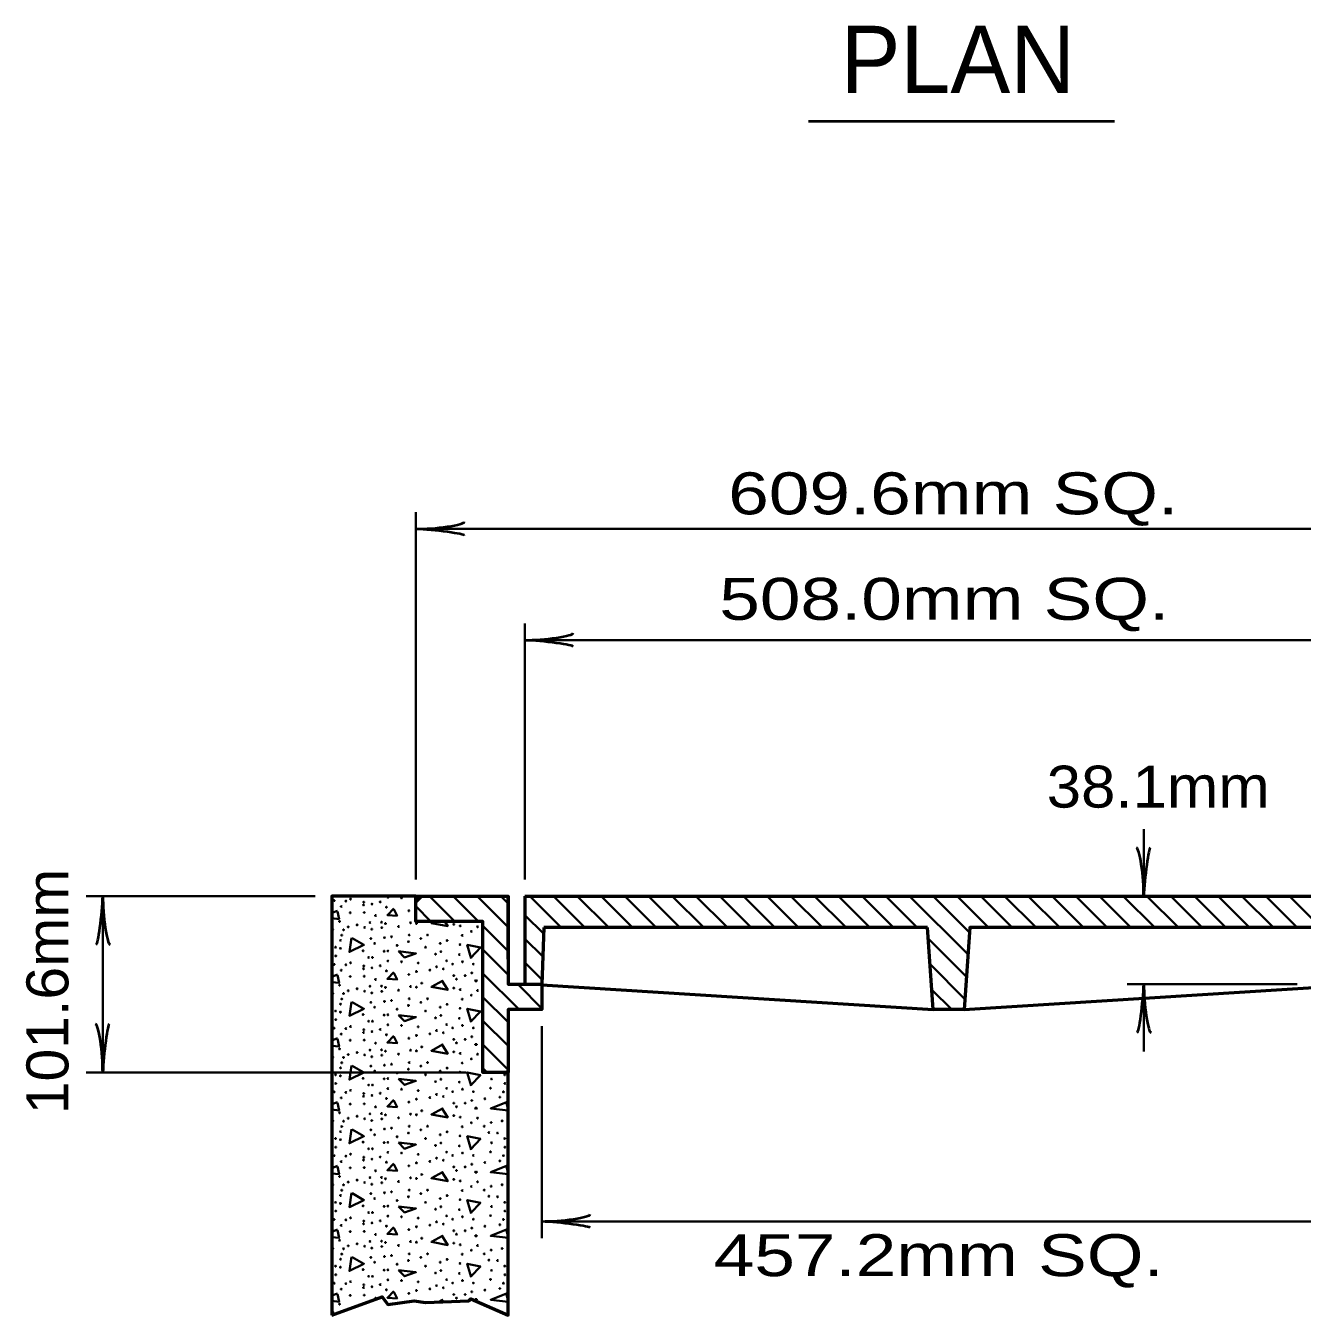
# Model space of a CAD drawing. Extents: x 918 to 1774, y -8 to 536.
# Drawn here: x 1316.9 to 1408.1, y 260.9 to 353.1 of the extents above; entities that cross this region are included whole.
import ezdxf

# ---------------------------------------------------------------- set-up
doc = ezdxf.new("R2010")
doc.units = 0
doc.header["$LTSCALE"] = 1.2
doc.layers.add('1', color=7, linetype='Continuous', lineweight=35)

msp = doc.modelspace()

# ---------------------------------------------------------------- linework, layer by layer
at = {"layer": '1', "lineweight": 40}
msp.add_line((1372.846, 346.241), (1394.731, 346.241), dxfattribs=at)
at = {"layer": '1'}
for p, q in [((1344.782, 292.018), (1344.782, 318.275)), ((1344.782, 317.075), (1420.982, 317.075)), ((1352.582, 292.018), (1352.582, 310.322)), ((1352.582, 309.122), (1413.182, 309.122)), ((1396.822, 290.818), (1396.822, 295.618)), ((1337.582, 290.818), (1321.204, 290.818)), ((1322.404, 290.818), (1322.404, 278.218)), ((1347.562, 289.018), (1345.762, 290.818)), ((1349.259, 289.018), (1347.459, 290.818)), ((1351.382, 288.591), (1349.156, 290.818)), ((1351.382, 290.288), (1350.853, 290.818)), ((1352.927, 290.818), (1355.177, 288.568)), ((1354.624, 290.818), (1356.874, 288.568)), ((1356.322, 290.818), (1358.572, 288.568)), ((1358.019, 290.818), (1360.269, 288.568)), ((1359.716, 290.818), (1361.966, 288.568)), ((1361.413, 290.818), (1363.663, 288.568)), ((1363.11, 290.818), (1365.36, 288.568)), ((1364.807, 290.818), (1367.057, 288.568)), ((1366.504, 290.818), (1368.754, 288.568)), ((1368.201, 290.818), (1370.451, 288.568)), ((1369.898, 290.818), (1372.148, 288.568)), ((1371.595, 290.818), (1373.845, 288.568)), ((1373.292, 290.818), (1375.542, 288.568)), ((1374.989, 290.818), (1377.239, 288.568)), ((1376.686, 290.818), (1378.936, 288.568)), ((1378.383, 290.818), (1380.633, 288.568)), ((1380.08, 290.818), (1384.26, 286.638)), ((1381.777, 290.818), (1384.369, 288.226)), ((1383.474, 290.818), (1385.724, 288.568)), ((1385.171, 290.818), (1387.421, 288.568)), ((1386.869, 290.818), (1389.119, 288.568)), ((1388.566, 290.818), (1390.816, 288.568)), ((1390.263, 290.818), (1392.513, 288.568)), ((1391.96, 290.818), (1394.21, 288.568)), ((1393.657, 290.818), (1395.907, 288.568)), ((1395.354, 290.818), (1397.604, 288.568)), ((1397.051, 290.818), (1399.301, 288.568)), ((1398.748, 290.818), (1400.998, 288.568)), ((1400.445, 290.818), (1402.695, 288.568)), ((1402.142, 290.818), (1404.392, 288.568)), ((1403.839, 290.818), (1406.089, 288.568)), ((1405.536, 290.818), (1407.786, 288.568)), ((1407.233, 290.818), (1409.483, 288.568)), ((1339.172, 289.778), (1338.782, 289.621)), ((1345.865, 289.018), (1344.782, 290.1)), ((1351.382, 286.894), (1349.582, 288.694)), ((1352.582, 289.466), (1353.921, 288.127)), ((1352.582, 287.769), (1353.858, 286.493)), ((1381.427, 287.774), (1384.15, 285.051)), ((1351.382, 285.197), (1349.582, 286.997)), ((1352.582, 286.072), (1353.796, 284.858)), ((1381.552, 285.952), (1384.041, 283.463)), ((1339.172, 285.218), (1338.782, 285.061)), ((1352.165, 282.718), (1349.582, 285.3)), ((1353.862, 282.718), (1352.062, 284.518)), ((1381.678, 284.128), (1383.089, 282.718)), ((1407.782, 284.518), (1395.623, 284.518)), ((1396.822, 279.718), (1396.822, 284.518)), ((1351.382, 281.803), (1349.582, 283.603)), ((1351.382, 280.106), (1349.582, 281.906)), ((1353.782, 281.518), (1353.782, 266.367)), ((1339.172, 280.658), (1338.782, 280.501)), ((1351.382, 278.409), (1349.582, 280.209)), ((1349.877, 278.218), (1349.582, 278.512)), ((1348.382, 278.218), (1321.204, 278.218)), ((1339.172, 276.098), (1338.782, 275.941)), ((1351.382, 275.526), (1351.268, 276.05)), ((1339.172, 271.538), (1338.782, 271.381)), ((1351.382, 270.966), (1351.268, 271.49)), ((1353.782, 267.567), (1411.982, 267.567)), ((1339.172, 266.978), (1338.782, 266.821)), ((1351.382, 266.406), (1351.268, 266.93)), ((1339.172, 262.418), (1338.782, 262.261)), ((1346.684, 261.962), (1346.38, 261.796)), ((1346.748, 261.812), (1346.636, 261.986)), ((1351.382, 261.846), (1351.268, 262.37))]:
    msp.add_line(p, q, dxfattribs=at)
at = {"layer": '1', "lineweight": 53}
for p, q in [((1345.187, 290.818), (1344.782, 290.413)), ((1351.382, 286.318), (1351.382, 290.818)), ((1352.582, 290.818), (1413.182, 290.818)), ((1352.582, 290.818), (1352.582, 284.518)), ((1353.938, 288.568), (1353.782, 284.495)), ((1381.372, 288.568), (1353.938, 288.568)), ((1353.783, 284.48), (1381.775, 282.718)), ((1383.989, 282.718), (1411.982, 284.48)), ((1351.382, 278.345), (1351.255, 278.218))]:
    msp.add_line(p, q, dxfattribs=at)
for points in [[(1344.782, 290.818), (1338.782, 290.818), (1338.782, 260.855)], [(1338.782, 260.855), (1342.37, 262.162), (1342.775, 261.622), (1344.663, 261.892), (1344.663, 261.892), (1345.473, 261.757), (1348.575, 261.892), (1348.71, 262.027), (1351.382, 260.855), (1351.382, 278.218), (1349.582, 278.218), (1349.582, 289.018), (1344.782, 289.018), (1344.782, 290.818)], [(1411.827, 288.568), (1384.393, 288.568), (1383.989, 282.718), (1381.775, 282.718), (1381.372, 288.568)]]:
    msp.add_lwpolyline(points, dxfattribs=at)
msp.add_lwpolyline([(1344.782, 290.818), (1351.382, 290.818), (1351.382, 284.518), (1353.783, 284.518), (1353.783, 282.718), (1351.382, 282.718), (1351.382, 278.218), (1349.582, 278.218), (1349.582, 289.018), (1344.782, 289.018)], close=True, dxfattribs=at)
at = {"layer": '1'}
for points in [[(1338.782, 289.237), (1339.292, 289.178), (1339.172, 289.73)], [(1343.204, 289.946), (1342.748, 289.466), (1343.444, 289.418), (1343.204, 289.898)], [(1346.126, 289.018), (1345.892, 288.89), (1347.068, 288.674), (1346.848, 289.018)], [(1340.228, 287.81), (1341.068, 287.33), (1340.036, 286.826), (1340.18, 287.834)], [(1348.748, 286.37), (1348.46, 287.33), (1349.396, 287.138), (1348.724, 286.418)], [(1338.782, 284.677), (1339.292, 284.618), (1339.172, 285.17)], [(1343.204, 285.386), (1342.748, 284.906), (1343.444, 284.858), (1343.204, 285.338)], [(1346.684, 284.762), (1345.892, 284.33), (1347.068, 284.114), (1346.636, 284.786)], [(1340.228, 283.25), (1341.068, 282.77), (1340.036, 282.266), (1340.18, 283.274)], [(1348.748, 281.81), (1348.46, 282.77), (1349.396, 282.578), (1348.724, 281.858)], [(1338.782, 280.117), (1339.292, 280.058), (1339.172, 280.61)], [(1343.204, 280.826), (1342.748, 280.346), (1343.444, 280.298), (1343.204, 280.778)], [(1346.684, 280.202), (1345.892, 279.77), (1347.068, 279.554), (1346.636, 280.226)], [(1340.228, 278.69), (1341.068, 278.21), (1340.036, 277.706), (1340.18, 278.714)], [(1348.748, 277.25), (1348.46, 278.21), (1349.396, 278.018), (1348.724, 277.298)], [(1338.782, 275.557), (1339.292, 275.498), (1339.172, 276.05)], [(1343.204, 276.266), (1342.748, 275.786), (1343.444, 275.738), (1343.204, 276.218)], [(1351.268, 276.098), (1350.14, 275.642), (1351.382, 275.499)], [(1346.684, 275.642), (1345.892, 275.21), (1347.068, 274.994), (1346.636, 275.666)], [(1340.228, 274.13), (1341.068, 273.65), (1340.036, 273.146), (1340.18, 274.154)], [(1348.748, 272.69), (1348.46, 273.65), (1349.396, 273.458), (1348.724, 272.738)], [(1338.782, 270.997), (1339.292, 270.938), (1339.172, 271.49)], [(1343.204, 271.706), (1342.748, 271.226), (1343.444, 271.178), (1343.204, 271.658)], [(1346.684, 271.082), (1345.892, 270.65), (1347.068, 270.434), (1346.636, 271.106)], [(1351.268, 271.538), (1350.14, 271.082), (1351.382, 270.939)], [(1340.228, 269.57), (1341.068, 269.09), (1340.036, 268.586), (1340.18, 269.594)], [(1348.748, 268.13), (1348.46, 269.09), (1349.396, 268.898), (1348.724, 268.178)], [(1338.782, 266.437), (1339.292, 266.378), (1339.172, 266.93)], [(1343.204, 267.146), (1342.748, 266.666), (1343.444, 266.618), (1343.204, 267.098)], [(1346.684, 266.522), (1345.892, 266.09), (1347.068, 265.874), (1346.636, 266.546)], [(1351.268, 266.978), (1350.14, 266.522), (1351.382, 266.379)], [(1340.228, 265.01), (1341.068, 264.53), (1340.036, 264.026), (1340.18, 265.034)], [(1348.748, 263.57), (1348.46, 264.53), (1349.396, 264.338), (1348.724, 263.618)], [(1338.782, 261.877), (1339.292, 261.818), (1339.172, 262.37)], [(1343.204, 262.586), (1342.748, 262.106), (1343.444, 262.058), (1343.204, 262.538)], [(1351.268, 262.418), (1350.14, 261.962), (1351.382, 261.819)]]:
    msp.add_lwpolyline(points, dxfattribs=at)
for points in [[(1343.54, 286.874), (1344.788, 286.73), (1343.972, 286.442)], [(1343.54, 282.314), (1344.788, 282.17), (1343.972, 281.882)], [(1343.54, 277.754), (1344.788, 277.61), (1343.972, 277.322)], [(1343.54, 273.194), (1344.788, 273.05), (1343.972, 272.762)], [(1343.54, 268.634), (1344.788, 268.49), (1343.972, 268.202)], [(1343.54, 264.074), (1344.788, 263.93), (1343.972, 263.642)]]:
    msp.add_lwpolyline(points, close=True, dxfattribs=at)
for centre in [(1338.944, 290.502), (1339.787, 290.47), (1340.121, 290.614), (1342.236, 290.407), (1342.786, 290.741), (1343.756, 290.693), (1339.453, 290.079), (1340.089, 289.633), (1341.044, 290.19), (1341.06, 290.391), (1341.091, 289.649), (1341.648, 290.254), (1342.675, 290.031), (1344.281, 289.776), (1339.326, 289.013), (1339.946, 288.615), (1340.582, 288.758), (1341.123, 288.583), (1341.505, 288.933), (1341.902, 289.426), (1342.332, 288.949), (1342.348, 288.567), (1342.611, 288.854), (1343.55, 288.647), (1344.408, 288.917), (1344.822, 288.87), (1347.494, 288.806), (1347.955, 288.695), (1349.195, 288.631), (1338.849, 288.424), (1339.405, 287.66), (1339.485, 288.026), (1339.612, 288.408), (1341.568, 287.788), (1341.632, 288.456), (1342.539, 287.851), (1343.041, 287.915), (1344.313, 288.042), (1345.14, 287.788), (1345.617, 288.042), (1347.017, 287.645), (1348.098, 288.01), (1348.75, 288.297), (1339.04, 287.167), (1339.39, 287.088), (1341.012, 286.913), (1341.839, 287.438), (1342.515, 286.878), (1342.786, 286.897), (1343.438, 287.295), (1344.249, 287.565), (1345.474, 287.167), (1346.524, 287.438), (1346.571, 286.849), (1347.939, 287.358), (1338.944, 285.942), (1339.056, 286.547), (1339.787, 285.91), (1340.121, 286.054), (1341.06, 285.831), (1341.409, 286.435), (1341.68, 286.435), (1342.236, 285.847), (1342.786, 286.181), (1343.756, 286.133), (1344.949, 286.038), (1346.19, 286.674), (1346.985, 286.197), (1347.414, 285.958), (1347.891, 286.642), (1348.114, 286.133), (1348.893, 285.958), (1339.453, 285.519), (1340.089, 285.073), (1341.044, 285.63), (1341.091, 285.089), (1341.648, 285.694), (1341.902, 284.866), (1342.675, 285.471), (1344.281, 285.216), (1344.822, 285.423), (1345.792, 285.534), (1346.269, 285.767), (1346.746, 285.614), (1347.494, 285.137), (1347.685, 284.882), (1348.305, 285.137), (1348.782, 285.328), (1339.326, 284.453), (1339.946, 284.055), (1340.582, 284.198), (1341.123, 284.023), (1341.505, 284.373), (1342.332, 284.389), (1342.348, 284.007), (1342.611, 284.294), (1343.55, 284.087), (1344.408, 284.357), (1344.822, 284.31), (1345.204, 284.596), (1347.494, 284.246), (1347.955, 284.135), (1349.052, 284.771), (1349.116, 284.771), (1349.195, 284.071), (1338.849, 283.864), (1339.405, 283.1), (1339.485, 283.466), (1339.612, 283.848), (1341.568, 283.228), (1341.632, 283.896), (1342.539, 283.291), (1343.041, 283.355), (1344.313, 283.482), (1345.14, 283.228), (1345.617, 283.482), (1347.017, 283.085), (1348.098, 283.45), (1348.75, 283.737), (1339.04, 282.607), (1339.39, 282.528), (1341.012, 282.353), (1341.839, 282.878), (1342.515, 282.318), (1342.786, 282.337), (1343.438, 282.735), (1344.249, 283.005), (1345.474, 282.607), (1346.19, 282.114), (1346.524, 282.878), (1346.571, 282.289), (1347.939, 282.798), (1338.944, 281.382), (1339.056, 281.987), (1339.787, 281.35), (1340.121, 281.494), (1341.06, 281.271), (1341.409, 281.875), (1341.68, 281.875), (1342.236, 281.287), (1342.786, 281.621), (1343.756, 281.573), (1344.949, 281.478), (1346.269, 281.207), (1346.985, 281.637), (1347.414, 281.398), (1347.891, 282.082), (1348.114, 281.573), (1348.893, 281.398), (1339.453, 280.959), (1340.089, 280.513), (1341.044, 281.07), (1341.091, 280.529), (1341.648, 281.134), (1341.902, 280.306), (1342.675, 280.911), (1344.281, 280.656), (1344.822, 280.863), (1345.792, 280.974), (1346.746, 281.054), (1347.494, 280.577), (1347.685, 280.322), (1348.305, 280.577), (1348.782, 280.768), (1339.326, 279.893), (1339.946, 279.495), (1340.582, 279.638), (1341.123, 279.463), (1341.505, 279.813), (1341.632, 279.336), (1342.332, 279.829), (1342.348, 279.447), (1342.611, 279.734), (1343.55, 279.527), (1344.408, 279.797), (1344.822, 279.75), (1345.204, 280.036), (1347.494, 279.686), (1347.955, 279.575), (1349.052, 280.211), (1349.116, 280.211), (1349.195, 279.511), (1338.849, 279.304), (1339.405, 278.54), (1339.485, 278.906), (1339.612, 279.288), (1341.568, 278.668), (1342.539, 278.731), (1343.041, 278.795), (1344.249, 278.445), (1344.313, 278.922), (1345.14, 278.668), (1345.617, 278.922), (1347.017, 278.525), (1348.098, 278.89), (1348.75, 279.177), (1339.04, 278.047), (1339.39, 277.968), (1341.012, 277.793), (1341.839, 278.318), (1342.515, 277.758), (1342.786, 277.777), (1343.438, 278.175), (1345.474, 278.047), (1346.19, 277.554), (1346.524, 278.318), (1346.571, 277.729), (1347.891, 277.522), (1347.939, 278.238), (1350.197, 277.745), (1351.136, 278.047), (1338.944, 276.822), (1339.056, 277.427), (1339.787, 276.79), (1340.121, 276.934), (1341.06, 276.711), (1341.409, 277.315), (1341.648, 276.574), (1341.68, 277.315), (1342.236, 276.727), (1342.786, 277.061), (1343.756, 277.013), (1344.949, 276.918), (1346.269, 276.647), (1346.985, 277.077), (1347.414, 276.838), (1348.114, 277.013), (1348.893, 276.838), (1350.118, 277.093), (1351.04, 276.822), (1351.152, 277.427), (1339.453, 276.399), (1340.089, 275.953), (1341.044, 276.51), (1341.091, 275.969), (1341.902, 275.746), (1342.675, 276.351), (1344.281, 276.096), (1344.822, 276.303), (1345.792, 276.414), (1346.746, 276.494), (1347.494, 276.017), (1347.685, 275.762), (1348.305, 276.017), (1348.782, 276.208), (1349.052, 275.651), (1349.116, 275.651), (1349.72, 276.335), (1350.786, 276.446), (1338.849, 274.744), (1339.326, 275.333), (1339.612, 274.728), (1339.946, 274.935), (1340.582, 275.078), (1341.123, 274.903), (1341.505, 275.253), (1341.632, 274.776), (1342.332, 275.269), (1342.348, 274.887), (1342.611, 275.174), (1343.55, 274.967), (1344.408, 275.237), (1344.822, 275.19), (1345.204, 275.476), (1347.494, 275.126), (1347.955, 275.015), (1349.195, 274.951), (1350.945, 274.744), (1339.405, 273.98), (1339.485, 274.346), (1341.568, 274.108), (1342.539, 274.171), (1343.041, 274.235), (1344.249, 273.885), (1344.313, 274.362), (1345.14, 274.108), (1345.617, 274.362), (1347.017, 273.965), (1348.098, 274.33), (1348.75, 274.617), (1349.673, 274.362), (1350.007, 273.917), (1350.166, 274.633), (1350.627, 273.885), (1339.04, 273.487), (1339.39, 273.408), (1341.012, 273.233), (1341.839, 273.758), (1342.515, 273.198), (1342.786, 273.217), (1343.438, 273.615), (1345.474, 273.487), (1346.19, 272.994), (1346.524, 273.758), (1346.571, 273.169), (1347.891, 272.962), (1347.939, 273.678), (1350.197, 273.185), (1351.136, 273.487), (1338.944, 272.262), (1339.056, 272.867), (1339.787, 272.23), (1340.121, 272.374), (1341.06, 272.151), (1341.409, 272.755), (1341.648, 272.014), (1341.68, 272.755), (1342.236, 272.167), (1342.786, 272.501), (1343.756, 272.453), (1344.949, 272.358), (1346.269, 272.087), (1346.985, 272.517), (1347.414, 272.278), (1348.114, 272.453), (1348.893, 272.278), (1350.118, 272.533), (1351.04, 272.262), (1351.152, 272.867), (1339.453, 271.839), (1340.089, 271.393), (1341.044, 271.95), (1341.091, 271.409), (1341.902, 271.186), (1342.675, 271.791), (1344.281, 271.536), (1344.822, 271.743), (1345.792, 271.854), (1346.746, 271.934), (1347.494, 271.457), (1347.685, 271.202), (1348.305, 271.457), (1348.782, 271.648), (1349.052, 271.091), (1349.116, 271.091), (1349.72, 271.775), (1350.786, 271.886), (1338.849, 270.184), (1339.326, 270.773), (1339.612, 270.168), (1339.946, 270.375), (1340.582, 270.518), (1341.123, 270.343), (1341.505, 270.693), (1341.632, 270.216), (1342.332, 270.709), (1342.348, 270.327), (1342.611, 270.614), (1343.55, 270.407), (1344.408, 270.677), (1344.822, 270.63), (1345.204, 270.916), (1347.494, 270.566), (1347.955, 270.455), (1349.195, 270.391), (1350.945, 270.184), (1339.405, 269.42), (1339.485, 269.786), (1341.568, 269.548), (1341.839, 269.198), (1342.539, 269.611), (1343.041, 269.675), (1344.249, 269.325), (1344.313, 269.802), (1345.14, 269.548), (1345.617, 269.802), (1346.524, 269.198), (1347.017, 269.405), (1348.098, 269.77), (1348.75, 270.057), (1349.673, 269.802), (1350.007, 269.357), (1350.166, 270.073), (1350.627, 269.325), (1339.04, 268.927), (1339.056, 268.307), (1339.39, 268.848), (1341.012, 268.673), (1342.515, 268.638), (1342.786, 268.657), (1343.438, 269.055), (1345.474, 268.927), (1346.19, 268.434), (1346.571, 268.609), (1347.891, 268.402), (1347.939, 269.118), (1350.197, 268.625), (1351.136, 268.927), (1351.152, 268.307), (1338.944, 267.702), (1339.787, 267.67), (1340.121, 267.814), (1341.044, 267.39), (1341.06, 267.591), (1341.409, 268.195), (1341.648, 267.454), (1341.68, 268.195), (1342.236, 267.607), (1342.786, 267.941), (1343.756, 267.893), (1344.949, 267.798), (1346.269, 267.527), (1346.746, 267.374), (1346.985, 267.957), (1347.414, 267.718), (1348.114, 267.893), (1348.893, 267.718), (1350.118, 267.973), (1351.04, 267.702), (1339.453, 267.279), (1340.089, 266.833), (1341.091, 266.849), (1341.902, 266.626), (1342.675, 267.231), (1344.281, 266.976), (1344.822, 267.183), (1345.792, 267.294), (1347.494, 266.897), (1347.685, 266.642), (1348.305, 266.897), (1348.782, 267.088), (1349.052, 266.531), (1349.116, 266.531), (1349.72, 267.215), (1350.786, 267.326), (1338.849, 265.624), (1339.326, 266.213), (1339.612, 265.608), (1339.946, 265.815), (1340.582, 265.958), (1341.123, 265.783), (1341.505, 266.133), (1341.632, 265.656), (1342.332, 266.149), (1342.348, 265.767), (1342.611, 266.054), (1343.55, 265.847), (1344.408, 266.117), (1344.822, 266.07), (1345.204, 266.356), (1347.494, 266.006), (1347.955, 265.895), (1349.195, 265.831), (1350.166, 265.513), (1350.945, 265.624), (1339.405, 264.86), (1339.485, 265.226), (1341.568, 264.988), (1341.839, 264.638), (1342.539, 265.051), (1343.041, 265.115), (1344.249, 264.765), (1344.313, 265.242), (1345.14, 264.988), (1345.617, 265.242), (1346.524, 264.638), (1347.017, 264.845), (1348.098, 265.21), (1348.75, 265.497), (1349.673, 265.242), (1350.007, 264.797), (1350.627, 264.765), (1339.04, 264.367), (1339.056, 263.747), (1339.39, 264.288), (1341.012, 264.113), (1342.515, 264.078), (1342.786, 264.097), (1343.438, 264.495), (1345.474, 264.367), (1346.19, 263.874), (1346.571, 264.049), (1347.891, 263.842), (1347.939, 264.558), (1350.197, 264.065), (1351.136, 264.367), (1351.152, 263.747), (1338.944, 263.142), (1339.787, 263.11), (1340.121, 263.254), (1341.044, 262.83), (1341.06, 263.031), (1341.409, 263.635), (1341.648, 262.894), (1341.68, 263.635), (1342.236, 263.047), (1342.786, 263.381), (1343.756, 263.333), (1344.949, 263.238), (1345.792, 262.734), (1346.269, 262.967), (1346.746, 262.814), (1346.985, 263.397), (1347.414, 263.158), (1348.114, 263.333), (1348.893, 263.158), (1350.118, 263.413), (1350.786, 262.766), (1351.04, 263.142), (1339.453, 262.719), (1340.089, 262.273), (1341.091, 262.289), (1341.902, 262.066), (1342.675, 262.671), (1344.281, 262.416), (1344.822, 262.623), (1347.494, 262.337), (1347.685, 262.082), (1348.305, 262.337), (1348.782, 262.528), (1349.052, 261.971), (1349.116, 261.971), (1349.72, 262.655), (1338.849, 261.064), (1339.326, 261.653)]:
    msp.add_circle(centre, 0.0318, dxfattribs=at)
for centre, start, end in [((1339.946, 261.255), 65.54995, 154.45857), ((1345.204, 261.796), 0.77566, 160.2951), ((1350.945, 261.064), 306.73512, 185.92765)]:
    msp.add_arc(centre, 0.0318, start, end, dxfattribs=at)
at = {"layer": '1', "lineweight": 40}
for centre, major_axis, ratio, start_param, end_param in [((1346.102, 317.397), (-2.143, -0.187), 0.122415, 0.896353, 3.141593), ((1346.138, 316.812), (-2.108, 0.211), 0.07063, 3.140715, 5.41811), ((1353.927, 308.868), (-2.108, 0.211), 0.07063, 3.140715, 5.41811), ((1353.892, 309.453), (-2.143, -0.187), 0.122415, 0.896353, 3.141593), ((1396.491, 292.127), (0.187, -2.143), 0.122415, 0.896353, 3.141593), ((1397.076, 292.162), (-0.211, -2.108), 0.07063, 3.140715, 5.41811), ((1322.15, 289.473), (0.211, 2.108), 0.07063, 3.140715, 5.41811), ((1322.15, 289.473), (0.211, 2.108), 0.07063, 3.140715, 5.41811), ((1322.735, 289.508), (-0.187, 2.143), 0.122415, 0.896353, 3.141593), ((1322.735, 289.508), (-0.187, 2.143), 0.122415, 0.896353, 3.141593), ((1396.569, 283.173), (0.211, 2.108), 0.07063, 3.140715, 5.41811), ((1397.154, 283.208), (-0.187, 2.143), 0.122415, 0.896353, 3.141593), ((1322.072, 279.527), (0.187, -2.143), 0.122415, 0.896353, 3.141593), ((1322.658, 279.562), (-0.211, -2.108), 0.07063, 3.140715, 5.41811), ((1355.102, 267.889), (-2.143, -0.187), 0.122415, 0.896353, 3.141593), ((1355.138, 267.303), (-2.108, 0.211), 0.07063, 3.140715, 5.41811)]:
    msp.add_ellipse(centre, major_axis=major_axis, ratio=ratio, start_param=start_param, end_param=end_param, dxfattribs=at)

# ---------------------------------------------------------------- texts
at = {"layer": '1'}
msp.add_text('PLAN', height=4.8, dxfattribs=at).set_placement((1375.145, 348.253))
for s, width, p in [('609.6mm SQ.', 1.3, (1367.117, 318.12)), ('508.0mm SQ.', 1.3, (1366.477, 310.578)), ('38.1mm', 1.1, (1389.884, 297.15)), ('457.2mm SQ.', 1.3, (1366.081, 263.648))]:
    msp.add_text(s, height=3, dxfattribs=dict(at, width=width)).set_placement(p)
at = {"layer": '1', "width": 1.05}
msp.add_text('101.6mm', height=3, rotation=90, dxfattribs=at).set_placement((1319.942, 275.223))

doc.saveas('drawing.dxf')
